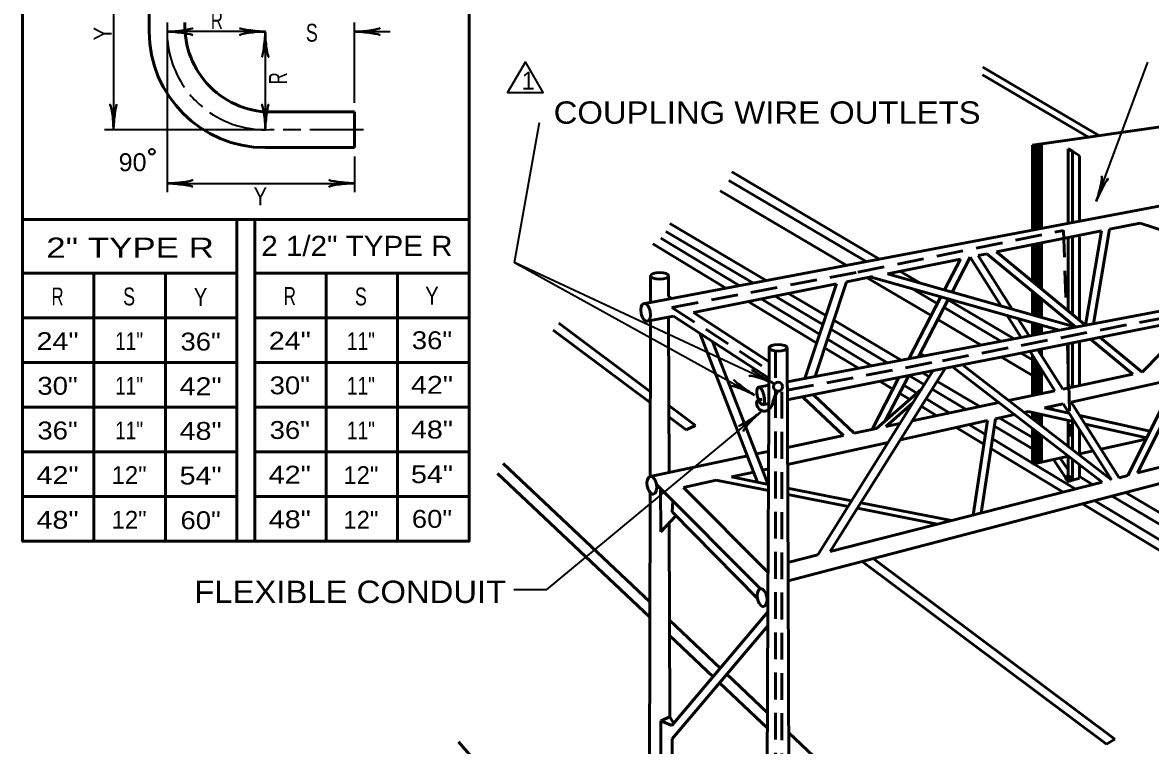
# Model space of a CAD drawing. Extents: x -68 to 612, y -58 to 382.
# Drawn here: x 289.7 to 416, y 204.4 to 285.4 of the extents above; entities that cross this region are included whole.
import ezdxf
from ezdxf.enums import TextEntityAlignment as Align

# ---------------------------------------------------------------- set-up
doc = ezdxf.new("R2010")
doc.units = 0
doc.header["$PDMODE"] = 32
doc.header["$PDSIZE"] = 0.5
doc.linetypes.add('MEDIUM_DASHED', pattern=[4.5, 3, -1.5])
doc.layers.add('1', color=7, linetype='Continuous', lineweight=53)

msp = doc.modelspace()

# ---------------------------------------------------------------- linework, layer by layer
at = {"layer": '1', "lineweight": 35}
for p, q in [((299.841, 294.371), (299.841, 273.36)), ((305.841, 285.371), (305.841, 284.371)), ((305.841, 284.373), (305.841, 266.371)), ((316.841, 284.36), (305.841, 284.36)), ((316.841, 284.36), (316.841, 273.371)), ((326.841, 276.371), (326.841, 285.36)), ((326.841, 284.36), (330.841, 284.36)), ((409.892, 265.358), (415.68, 280.949)), ((344.75, 258.527), (347.553, 274.168)), ((316.74, 273.36), (298.841, 273.36)), ((320.841, 273.371), (318.841, 273.371)), ((327.841, 273.371), (321.841, 273.371)), ((326.841, 270.371), (326.841, 266.371)), ((305.841, 267.371), (326.841, 267.371))]:
    msp.add_line(p, q, dxfattribs=at)
at = {"layer": '1'}
for p, q in [((303.841, 294.371), (303.841, 284.371)), ((397.171, 279.535), (409.017, 272.54)), ((397.183, 280.395), (410.199, 272.709)), ((402.759, 271.646), (445.759, 277.79)), ((326.841, 275.371), (317.841, 275.371)), ((326.841, 275.371), (326.841, 271.371)), ((402.759, 271.646), (402.759, 262.146)), ((402.825, 271.656), (402.825, 262.159)), ((402.918, 271.669), (402.918, 262.176)), ((403.041, 271.686), (403.041, 262.2)), ((403.09, 271.693), (403.09, 262.209)), ((403.09, 271.693), (403.09, 262.335)), ((403.09, 271.693), (403.09, 262.335)), ((403.211, 271.711), (403.211, 262.232)), ((403.272, 271.719), (403.272, 262.243)), ((403.393, 271.737), (403.393, 262.266)), ((403.393, 271.737), (403.393, 262.335)), ((403.442, 271.744), (403.442, 262.275)), ((403.575, 271.763), (403.575, 262.301)), ((403.575, 271.763), (403.575, 262.335)), ((403.689, 271.779), (403.689, 262.322)), ((403.759, 271.789), (403.759, 262.335)), ((326.841, 271.371), (316.841, 271.371)), ((406.759, 271.218), (406.759, 262.904)), ((407.259, 270.968), (407.259, 262.998)), ((408.009, 270.468), (408.009, 263.14)), ((369.087, 268.655), (385.61, 258.898)), ((368.75, 267.693), (384.121, 258.616)), ((367.796, 266.514), (381.887, 258.193)), ((289.661, 263.311), (339.661, 263.311)), ((313.661, 263.311), (313.661, 227.311)), ((315.661, 227.311), (315.661, 263.311)), ((362.13, 262.892), (372.953, 256.501)), ((375.293, 245.156), (470.608, 263.209)), ((411.394, 262.226), (414.827, 262.913)), ((414.827, 262.913), (434.736, 256.415)), ((361.708, 261.991), (371.449, 256.216)), ((398.734, 259.694), (410.501, 262.048)), ((408.687, 251.481), (410.501, 262.048)), ((409.578, 251.65), (411.394, 262.226)), ((360.227, 260.603), (368.429, 255.644)), ((361.133, 261.224), (369.901, 255.923)), ((402.759, 260.5), (402.759, 256.373)), ((402.825, 260.513), (402.825, 256.318)), ((402.949, 260.537), (402.949, 256.216)), ((403.09, 260.566), (403.09, 256.1)), ((403.09, 260.566), (403.09, 256.1)), ((403.09, 260.566), (403.09, 256.1)), ((403.09, 260.566), (403.09, 256.1)), ((403.272, 260.602), (403.272, 255.95)), ((403.272, 260.602), (403.272, 255.95)), ((403.332, 260.614), (403.332, 255.9)), ((403.454, 260.638), (403.454, 255.8)), ((403.454, 260.638), (403.454, 255.8)), ((403.535, 260.655), (403.535, 255.732)), ((403.636, 260.675), (403.636, 255.649)), ((403.759, 260.7), (403.759, 255.547)), ((406.759, 261.3), (406.759, 253.072)), ((407.259, 261.4), (407.259, 252.659)), ((408.009, 261.4), (408.009, 252.04)), ((393.758, 255.197), (395.785, 259.105)), ((395.785, 259.105), (399.256, 253.639)), ((396.679, 259.283), (397.659, 259.479)), ((396.679, 259.283), (400.484, 253.291)), ((397.659, 259.479), (407.601, 251.275)), ((398.734, 259.694), (408.687, 251.481)), ((386.511, 257.25), (394.685, 258.885)), ((392.898, 255.44), (394.685, 258.885)), ((289.661, 257.311), (313.661, 257.311)), ((297.661, 257.311), (297.661, 227.311)), ((305.661, 257.311), (305.661, 227.311)), ((315.661, 257.311), (339.661, 257.311)), ((323.661, 227.311), (323.661, 257.311)), ((331.661, 227.311), (331.661, 257.311)), ((359.997, 257.007), (359.997, 254.047)), ((362.017, 257.007), (362.017, 254.71)), ((381.94, 256.335), (384.882, 256.924)), ((384.251, 256.797), (391.409, 252.57)), ((384.683, 256.884), (384.882, 256.924)), ((384.683, 256.884), (405.732, 250.921)), ((386.511, 257.25), (407.601, 251.275)), ((387.923, 257.532), (390.144, 256.221)), ((364.795, 252.906), (380.797, 256.106)), ((380.797, 256.106), (377.277, 245.527)), ((381.94, 256.335), (378.417, 245.747)), ((389.24, 255.593), (392.101, 253.903)), ((402.759, 255.271), (402.759, 252.647)), ((402.8, 255.237), (402.8, 252.635)), ((402.85, 255.196), (402.85, 252.621)), ((362.017, 254.71), (362.337, 254.503)), ((370.929, 254.133), (378.598, 249.496)), ((372.382, 254.423), (378.922, 250.469)), ((373.945, 254.736), (379.287, 251.569)), ((375.437, 255.034), (379.619, 252.565)), ((388.901, 247.734), (392.499, 254.67)), ((389.993, 247.941), (393.358, 254.427)), ((393.317, 254.347), (400.724, 249.973)), ((402.923, 255.136), (402.923, 252.601)), ((402.978, 255.09), (402.978, 252.585)), ((403.039, 255.04), (403.039, 252.567)), ((403.128, 254.966), (403.128, 252.542)), ((403.178, 254.925), (403.178, 252.528)), ((403.256, 254.861), (403.256, 252.506)), ((403.323, 254.806), (403.323, 252.487)), ((403.423, 254.723), (403.423, 252.459)), ((403.529, 254.636), (403.529, 252.429)), ((403.606, 254.571), (403.606, 252.407)), ((403.673, 254.516), (403.673, 252.388)), ((403.718, 254.48), (403.718, 252.375)), ((403.759, 254.445), (403.759, 252.364)), ((364.795, 252.906), (373.257, 247.407)), ((392.856, 253.458), (399.235, 249.691)), ((414.527, 234.944), (423.425, 252.746)), ((289.661, 252.311), (313.661, 252.311)), ((315.661, 252.311), (339.661, 252.311)), ((349.699, 251.719), (359.979, 244.029)), ((359.617, 251.927), (362.57, 252.492)), ((359.997, 252.007), (359.957, 234.547)), ((362.017, 252.386), (362.057, 234.947)), ((362.57, 252.492), (373.243, 245.563)), ((375.302, 243.12), (420.898, 252.241)), ((380.51, 252.038), (388.067, 247.576)), ((392.164, 252.124), (397.001, 249.268)), ((399.94, 252.562), (401.492, 250.118)), ((401.168, 252.214), (402.39, 250.288)), ((402.759, 251.763), (402.759, 250.358)), ((402.803, 251.751), (402.803, 250.367)), ((402.851, 251.737), (402.851, 250.376)), ((402.91, 251.721), (402.91, 250.387)), ((402.957, 251.707), (402.957, 250.396)), ((403.042, 251.683), (403.042, 250.412)), ((403.128, 251.659), (403.128, 250.428)), ((403.207, 251.636), (403.207, 250.443)), ((403.282, 251.615), (403.282, 250.457)), ((403.351, 251.596), (403.351, 250.47)), ((403.393, 251.584), (403.393, 250.478)), ((403.463, 251.564), (403.463, 250.492)), ((403.532, 251.545), (403.532, 250.505)), ((403.611, 251.522), (403.611, 250.52)), ((403.686, 251.501), (403.686, 250.548)), ((403.718, 251.492), (403.718, 250.548)), ((403.759, 251.48), (403.759, 250.548)), ((413.438, 234.665), (422.369, 252.535)), ((415.055, 246.226), (420.898, 252.241)), ((349.1, 250.918), (359.976, 242.783)), ((371.983, 233.914), (365.506, 250.586)), ((380.178, 251.041), (386.518, 247.282)), ((410.328, 250.126), (415.055, 246.226)), ((373.193, 233.56), (366.94, 249.655)), ((373.257, 248.927), (373.137, 220.087)), ((375.277, 248.958), (375.387, 222.867)), ((379.486, 248.959), (383.276, 246.668)), ((379.81, 249.932), (384.748, 246.947)), ((406.759, 249.412), (406.759, 244.469)), ((407.259, 249.512), (407.259, 244.575)), ((408.009, 249.662), (408.009, 244.733)), ((409.253, 249.911), (413.992, 246.001)), ((375.388, 222.867), (474.259, 248.711)), ((390.195, 248.328), (390.635, 248.062)), ((399.287, 247.918), (402.759, 245.868)), ((401.491, 248.359), (402.759, 247.61)), ((402.483, 248.557), (405.278, 244.155)), ((402.759, 248.122), (402.759, 243.622)), ((402.817, 248.032), (402.817, 243.634)), ((402.868, 247.951), (402.868, 243.645)), ((402.92, 247.87), (402.92, 243.656)), ((402.963, 247.801), (402.963, 243.665)), ((402.999, 247.745), (402.999, 243.672)), ((403.062, 247.645), (403.062, 243.686)), ((403.376, 248.736), (406.166, 244.343)), ((403.423, 248.745), (403.423, 248.663)), ((403.463, 248.753), (403.463, 248.6)), ((403.514, 248.763), (403.514, 248.519)), ((403.554, 248.771), (403.554, 248.457)), ((403.609, 248.782), (403.609, 248.369)), ((403.633, 248.787), (403.633, 248.332)), ((403.673, 248.795), (403.673, 248.269)), ((403.724, 248.812), (403.724, 248.188)), ((403.759, 248.812), (403.759, 248.133)), ((289.661, 247.311), (313.661, 247.311)), ((315.661, 247.311), (339.661, 247.311)), ((378.714, 225.781), (391.614, 246.383)), ((380.117, 226.14), (392.97, 246.654)), ((410.557, 233.928), (393.808, 246.822)), ((411.603, 234.195), (394.913, 247.043)), ((403.122, 247.552), (403.122, 243.698)), ((403.161, 247.489), (403.161, 243.707)), ((403.205, 247.42), (403.205, 243.716)), ((403.249, 247.352), (403.249, 243.725)), ((403.276, 247.308), (403.276, 243.731)), ((403.324, 247.233), (403.324, 243.741)), ((403.356, 247.183), (403.356, 243.748)), ((403.411, 247.096), (403.411, 243.76)), ((403.471, 247.002), (403.471, 243.772)), ((403.526, 246.915), (403.526, 243.784)), ((403.578, 246.834), (403.578, 243.795)), ((403.625, 246.759), (403.625, 243.805)), ((403.637, 246.74), (403.637, 243.808)), ((403.681, 246.671), (403.681, 243.817)), ((403.728, 246.596), (403.728, 243.833)), ((403.759, 246.548), (403.759, 243.833)), ((384.794, 239.817), (387.805, 245.621)), ((385.704, 245.201), (387.137, 244.334)), ((386.281, 240.784), (388.904, 245.841)), ((388.915, 245.861), (390.645, 244.835)), ((390.474, 246.155), (391.202, 245.725)), ((392.067, 245.214), (396.874, 242.375)), ((406.166, 244.343), (413.992, 246.001)), ((407.088, 242.891), (418.846, 245.485)), ((372.077, 244.547), (373.237, 244.767)), ((385.296, 239.923), (390.32, 244.317)), ((387.887, 243.88), (389.03, 243.189)), ((388.348, 244.77), (389.82, 243.88)), ((391.509, 244.323), (395.342, 242.051)), ((400.092, 243.057), (405.278, 244.155)), ((372.577, 242.587), (373.237, 242.707)), ((377.037, 243.427), (381.583, 239.137)), ((378.257, 243.667), (382.787, 239.392)), ((386.345, 240.145), (389.359, 242.781)), ((389.281, 240.767), (398.999, 242.825)), ((390.944, 243.201), (393.494, 241.659)), ((404.123, 242.237), (406.205, 242.696)), ((406.205, 242.696), (411.603, 234.195)), ((407.088, 242.891), (412.469, 234.417)), ((289.661, 242.311), (313.661, 242.311)), ((315.661, 242.311), (339.661, 242.311)), ((362.04, 242.488), (365.01, 240.266)), ((390.313, 242.414), (392.062, 241.356)), ((398.625, 241.024), (400.734, 241.489)), ((401.817, 241.728), (402.268, 241.828)), ((402.268, 241.828), (407.49, 240.673)), ((402.759, 241.719), (402.759, 241.004)), ((402.806, 241.709), (402.806, 240.968)), ((402.865, 241.696), (402.865, 240.922)), ((402.91, 241.686), (402.91, 240.888)), ((402.979, 241.67), (402.979, 240.834)), ((403.048, 241.655), (403.048, 240.781)), ((403.113, 241.641), (403.113, 240.731)), ((403.172, 241.628), (403.172, 240.686)), ((403.232, 241.615), (403.232, 240.64)), ((403.296, 241.6), (403.296, 240.59)), ((403.355, 241.587), (403.355, 240.544)), ((403.41, 241.575), (403.41, 240.503)), ((403.474, 241.561), (403.474, 240.453)), ((403.524, 241.55), (403.524, 240.415)), ((403.588, 241.536), (403.588, 240.365)), ((403.643, 241.524), (403.643, 240.323)), ((403.692, 241.513), (403.692, 240.285)), ((403.722, 241.506), (403.722, 240.262)), ((403.759, 241.498), (403.759, 240.234)), ((404.123, 242.237), (406.885, 241.626)), ((404.64, 242.351), (405.256, 241.986)), ((408.056, 241.367), (415.919, 239.628)), ((362.043, 241.237), (363.991, 239.78)), ((365.01, 240.266), (363.991, 239.78)), ((386.345, 240.145), (387.917, 240.478)), ((387.969, 238.673), (397.735, 240.827)), ((394.22, 240.052), (397.326, 238.174)), ((395.636, 240.364), (397.491, 239.243)), ((396.102, 230.23), (397.735, 240.827)), ((396.998, 230.459), (398.625, 241.024)), ((398.495, 240.181), (402.759, 237.654)), ((399.016, 241.11), (402.759, 238.9)), ((406.759, 240.834), (406.759, 237.924)), ((407.259, 241.036), (407.259, 237.539)), ((408.661, 240.414), (415.55, 238.891)), ((375.324, 237.811), (381.583, 239.137)), ((382.787, 239.392), (385.296, 239.923)), ((402.759, 239.931), (402.759, 235.933)), ((402.825, 239.88), (402.825, 235.947)), ((402.885, 239.834), (402.885, 235.96)), ((402.924, 239.803), (402.924, 235.969)), ((402.964, 239.773), (402.964, 235.978)), ((403.043, 239.712), (403.043, 235.996)), ((403.103, 239.666), (403.103, 236.009)), ((403.182, 239.605), (403.182, 236.026)), ((403.241, 239.559), (403.241, 236.039)), ((403.33, 239.491), (403.33, 236.059)), ((403.42, 239.422), (403.42, 236.079)), ((403.487, 239.371), (403.487, 236.094)), ((403.539, 239.331), (403.539, 236.105)), ((403.578, 239.3), (403.578, 236.114)), ((403.638, 239.254), (403.638, 236.127)), ((403.706, 239.202), (403.706, 236.142)), ((403.759, 239.161), (403.759, 236.154)), ((408.009, 239.855), (408.009, 236.962)), ((410.43, 237.628), (415.476, 238.743)), ((375.332, 235.885), (386.597, 238.37)), ((398.113, 237.698), (406.195, 232.812)), ((289.661, 237.311), (313.661, 237.311)), ((315.661, 237.311), (339.661, 237.311)), ((359.948, 234.555), (370.838, 236.861)), ((371.829, 237.071), (373.209, 237.363)), ((402.759, 235.933), (406.794, 236.824)), ((406.759, 233.981), (405.112, 236.453)), ((406.759, 235.295), (405.875, 236.621)), ((406.759, 236.852), (406.759, 234.367)), ((407.259, 236.467), (407.259, 234.135)), ((407.877, 237.064), (409.548, 237.433)), ((414.527, 234.944), (423.276, 237.182)), ((343.481, 236.017), (359.912, 220.526)), ((369.04, 234.497), (371.542, 235.049)), ((372.53, 235.267), (373.201, 235.415)), ((408.009, 235.889), (408.009, 234.367)), ((342.843, 234.901), (359.908, 218.812)), ((363.669, 233.312), (367.354, 234.125)), ((367.354, 234.125), (373.191, 232.967)), ((369.04, 234.497), (373.194, 233.673)), ((380.117, 226.14), (410.557, 233.928)), ((408.009, 234.541), (409.5, 233.657)), ((412.469, 234.417), (413.438, 234.665)), ((359.937, 232.747), (359.752, 145.28)), ((360.649, 233.662), (372.297, 221.987)), ((361.115, 233.194), (361.137, 228.367)), ((363.669, 233.312), (373.153, 223.808)), ((375.344, 233.247), (382.5, 231.828)), ((375.346, 232.54), (382.107, 231.199)), ((413.181, 232.745), (509.936, 175.609)), ((289.661, 232.311), (313.661, 232.311)), ((315.661, 232.311), (339.661, 232.311)), ((362.417, 230.607), (362.477, 231.83)), ((383.55, 231.619), (393.68, 229.61)), ((408.38, 231.491), (506.63, 172.091)), ((409.73, 231.843), (507.099, 172.976)), ((411.694, 232.357), (509.936, 174.113)), ((361.137, 228.367), (362.838, 230.151)), ((362.417, 230.607), (371.972, 220.9)), ((383.156, 230.991), (392.124, 229.212)), ((362.075, 229.351), (362.137, 207.627)), ((375.379, 224.927), (378.714, 225.781)), ((383.699, 225.039), (411.039, 204.589)), ((384.936, 225.362), (411.971, 205.141)), ((375.388, 222.867), (375.594, 172.678)), ((373.137, 220.087), (372.977, 179.527)), ((362.357, 206.687), (373.137, 219.387)), ((362.106, 218.457), (367.795, 213.094)), ((362.397, 205.187), (373.137, 217.827)), ((362.111, 216.735), (366.985, 212.139)), ((368.528, 212.403), (373.09, 208.102)), ((367.718, 211.449), (373.083, 206.391)), ((361.137, 207.207), (362.137, 207.627)), ((361.137, 207.207), (361.137, 201.667)), ((361.137, 207.207), (362.357, 206.687)), ((362.137, 207.627), (362.577, 206.947)), ((338.487, 204.854), (359.827, 180.306)), ((362.397, 205.187), (362.397, 203.447)), ((375.458, 205.87), (446.501, 138.892)), ((411.971, 205.141), (411.039, 204.589))]:
    msp.add_line(p, q, dxfattribs=at)
at = {"layer": '1', "linetype": 'MEDIUM_DASHED'}
for p, q in [((383.217, 257.427), (406.239, 262.092)), ((406.239, 262.092), (406.536, 253.256)), ((362.391, 253.481), (383.217, 257.427)), ((362.391, 253.481), (373.247, 246.428)), ((406.666, 249.394), (407.014, 239.028)), ((373.998, 248.603), (373.998, 172.185)), ((374.674, 244.047), (374.674, 172.394))]:
    msp.add_line(p, q, dxfattribs=at)
at = {"layer": '1'}
msp.add_lwpolyline([(339.661, 327.311), (289.661, 327.311), (289.661, 227.311), (339.661, 227.311)], close=True, dxfattribs=at)
for points in [[(359.251, 253.915), (359.997, 254.047), (510.13, 282.482)], [(406.759, 271.218), (407.259, 270.968), (408.009, 270.468)], [(398.277, 238.767), (402.759, 236.058), (407.553, 233.159)], [(406.759, 234.367), (406.759, 233.981), (408.009, 234.367)]]:
    msp.add_lwpolyline(points, dxfattribs=at)
at = {"layer": '1', "lineweight": 35}
msp.add_lwpolyline([(345.979, 280.987), (343.979, 277.523), (347.979, 277.523)], close=True, dxfattribs=at)
at = {"layer": '1', "linetype": 'MEDIUM_DASHED'}
msp.add_lwpolyline([(375.294, 244.216), (392.667, 247.516), (478.145, 264.087)], dxfattribs=at)
at = {"layer": '1', "lineweight": 35}
for points in [[(373.78, 244.968), (344.75, 258.527), (371.634, 243.668)], [(372.312, 241.748), (348.308, 221.861), (344.694, 221.861)]]:
    msp.add_lwpolyline(points, dxfattribs=at)
msp.add_circle((304.145, 270.909), 0.323, dxfattribs=at)
at = {"layer": '1'}
msp.add_circle((374.272, 244.6), 0.504, dxfattribs=at)
for centre, radius, start, end in [((316.853, 284.383), 13.012, 180.05297, 269.94703), ((317.471, 285.001), 9.637, 177.80196, 272.19803)]:
    msp.add_arc(centre, radius, start, end, dxfattribs=at)
at = {"layer": '1', "lineweight": 35}
for start, end in [(180.05297, 214.53594), (219.78967, 230.21033), (235.46406, 275.14734)]:
    msp.add_arc((316.853, 284.383), 11.012, start, end, dxfattribs=at)
at = {"layer": '1', "lineweight": 40}
for centre, major_axis, ratio, start_param, end_param in [((306.961, 284.148), (-1.756, 0.176), 0.07063, 3.1407148, 5.41811), ((306.961, 284.148), (-1.756, 0.176), 0.07063, 3.1407148, 5.41811), ((306.932, 284.636), (-1.786, -0.156), 0.122415, 0.8963533, 3.1415927), ((306.932, 284.636), (-1.786, -0.156), 0.122415, 0.8963533, 3.1415927), ((315.75, 284.083), (1.786, 0.156), 0.122415, 0.8963533, 3.1415927), ((315.75, 284.083), (1.786, 0.156), 0.122415, 0.8963533, 3.1415927), ((315.72, 284.571), (1.756, -0.176), 0.07063, 3.1407148, 5.41811), ((315.72, 284.571), (1.756, -0.176), 0.07063, 3.1407148, 5.41811), ((316.629, 283.239), (0.176, 1.756), 0.07063, 3.1407148, 5.41811), ((316.629, 283.239), (0.176, 1.756), 0.07063, 3.1407148, 5.41811), ((317.117, 283.269), (-0.156, 1.786), 0.122415, 0.8963533, 3.1415927), ((317.117, 283.269), (-0.156, 1.786), 0.122415, 0.8963533, 3.1415927), ((327.961, 284.148), (-1.756, 0.176), 0.07063, 3.1407148, 5.41811), ((327.961, 284.148), (-1.756, 0.176), 0.07063, 3.1407148, 5.41811), ((327.932, 284.636), (-1.786, -0.156), 0.122415, 0.8963533, 3.1415927), ((327.932, 284.636), (-1.786, -0.156), 0.122415, 0.8963533, 3.1415927), ((299.564, 274.451), (0.156, -1.786), 0.122415, 0.8963533, 3.1415927), ((299.564, 274.451), (0.156, -1.786), 0.122415, 0.8963533, 3.1415927), ((300.052, 274.48), (-0.176, -1.756), 0.07063, 3.1407148, 5.41811), ((300.052, 274.48), (-0.176, -1.756), 0.07063, 3.1407148, 5.41811), ((316.564, 274.462), (0.156, -1.786), 0.122415, 0.8963533, 3.1415927), ((316.564, 274.462), (0.156, -1.786), 0.122415, 0.8963533, 3.1415927), ((317.052, 274.492), (-0.176, -1.756), 0.07063, 3.1407148, 5.41811), ((317.052, 274.492), (-0.176, -1.756), 0.07063, 3.1407148, 5.41811), ((306.932, 267.647), (-1.786, -0.156), 0.122415, 0.8963533, 3.1415927), ((306.932, 267.647), (-1.786, -0.156), 0.122415, 0.8963533, 3.1415927), ((410.012, 266.478), (-0.475, -1.728), 0.122415, 0.8963533, 3.1415927), ((410.48, 266.335), (0.776, 1.585), 0.07063, 6.2823074, 8.5597026), ((306.961, 267.159), (-1.756, 0.176), 0.07063, 3.1407148, 5.41811), ((306.961, 267.159), (-1.756, 0.176), 0.07063, 3.1407148, 5.41811), ((325.75, 267.095), (1.786, 0.156), 0.122415, 0.8963533, 3.1415927), ((325.72, 267.583), (1.756, -0.176), 0.07063, 3.1407148, 5.41811), ((372.855, 245.634), (1.517, -0.902), 0.07063, 3.1407148, 5.41811), ((372.855, 245.634), (1.517, -0.902), 0.07063, 3.1407148, 5.41811), ((370.756, 244.396), (-1.452, 1.003), 0.07063, 6.2823074, 8.5597026), ((372.675, 245.179), (1.684, -0.614), 0.122415, 0.8963533, 3.1415927), ((372.675, 245.179), (1.684, -0.614), 0.122415, 0.8963533, 3.1415927), ((370.545, 243.955), (1.638, -0.727), 0.122415, 0.8963533, 3.1415927), ((371.314, 241.196), (-1.465, -0.985), 0.07063, 6.2823074, 8.5597026), ((371.648, 240.839), (1.275, 1.26), 0.122415, 0.8963533, 3.1415927)]:
    msp.add_ellipse(centre, major_axis=major_axis, ratio=ratio, start_param=start_param, end_param=end_param, dxfattribs=at)
at = {"layer": '1'}
for centre, major_axis, ratio in [((361.008, 257.009), (1.008, 0), 0.366793), ((359.438, 252.925), (0.188, -0.99), 0.516919), ((374.277, 248.958), (1.008, 0), 0.366793), ((372.329, 243.568), (0.252, -0.978), 0.357898), ((360.136, 233.565), (0.188, -0.99), 0.517636), ((372.485, 220.997), (0.188, -0.99), 0.517636)]:
    msp.add_ellipse(centre, major_axis=major_axis, ratio=ratio, dxfattribs=at)
msp.add_spline([(374.237, 244.167), (374.157, 243.987), (374.137, 243.927), (373.897, 243.527), (373.797, 243.207), (373.677, 242.847), (373.637, 242.647), (373.597, 242.527), (373.477, 242.307), (373.317, 242.167), (373.097, 241.967), (372.817, 241.867), (372.617, 241.867), (372.337, 241.967), (372.157, 242.107), (372.017, 242.327), (371.937, 242.427), (371.877, 242.687), (371.877, 242.927), (372.117, 243.107), (372.357, 243.187), (372.477, 243.187)], degree=3, dxfattribs=at)
msp.add_point((406.759, 234.367), dxfattribs=at)

# ---------------------------------------------------------------- texts
for s, height, width, p in [('R', 2, 0.7, (310.75, 284.654)), ('S', 2, 0.75, (321.387, 283.235)), ('COUPLING WIRE OUTLETS', 2.5, 1.1, (349.139, 274.046)), ('90', 2, 1.05, (300.422, 268.736)), ('Y', 2, 0.85, (315.537, 264.923)), ('2 1/2" TYPE R', 2.25, 1.1, (316.395, 259.247)), ('2" TYPE R', 2.25, 1.3, (292.312, 259.044)), ('FLEXIBLE CONDUIT', 2.5, 1.1, (308.886, 220.392))]:
    msp.add_text(s, height=height, dxfattribs=dict(at, width=width)).set_placement(p)
for s, width, p in [('Y', 0.85, (299.624, 283.368)), ('R', 0.7, (319.26, 278.446))]:
    msp.add_text(s, height=2, rotation=90, dxfattribs=dict(at, width=width)).set_placement(p)
msp.add_text('1', height=2, dxfattribs=at).set_placement((345.556, 277.861))
for s, width, p in [('R', 0.7, (293.58, 253.705)), ('S', 0.75, (301.591, 253.705)), ('Y', 0.85, (309.601, 253.655)), ('R', 0.7, (319.59, 253.756)), ('S', 0.75, (327.55, 253.705)), ('Y', 0.85, (335.51, 253.807)), ('24"', 1.2, (293.58, 248.705)), ('11"', 0.8, (301.591, 248.705)), ('36"', 1.15, (309.601, 248.655)), ('24"', 1.2, (319.59, 248.756)), ('11"', 0.8, (327.55, 248.705)), ('36"', 1.15, (335.51, 248.807)), ('30"', 1.15, (293.58, 243.705)), ('11"', 0.8, (301.591, 243.705)), ('42"', 1.2, (309.601, 243.655)), ('30"', 1.15, (319.59, 243.756)), ('11"', 0.8, (327.55, 243.705)), ('42"', 1.2, (335.51, 243.807)), ('36"', 1.15, (293.58, 238.705)), ('11"', 0.8, (301.591, 238.705)), ('48"', 1.2, (309.601, 238.655)), ('36"', 1.15, (319.59, 238.756)), ('11"', 0.8, (327.55, 238.705)), ('48"', 1.2, (335.51, 238.807)), ('42"', 1.2, (293.58, 233.705)), ('54"', 1.2, (309.601, 233.655)), ('42"', 1.2, (319.59, 233.756)), ('54"', 1.2, (335.51, 233.807)), ('48"', 1.2, (293.58, 228.705)), ('60"', 1.15, (309.601, 228.655)), ('48"', 1.2, (319.59, 228.756)), ('60"', 1.15, (335.51, 228.807))]:
    msp.add_text(s, height=2, dxfattribs=dict(at, width=width)).set_placement(p, align=Align.CENTER)
for p in [(301.591, 233.705), (327.55, 233.705), (301.591, 228.705), (327.55, 228.705)]:
    msp.add_text('12"', height=2, dxfattribs=at).set_placement(p, align=Align.CENTER)

doc.saveas('drawing.dxf')
